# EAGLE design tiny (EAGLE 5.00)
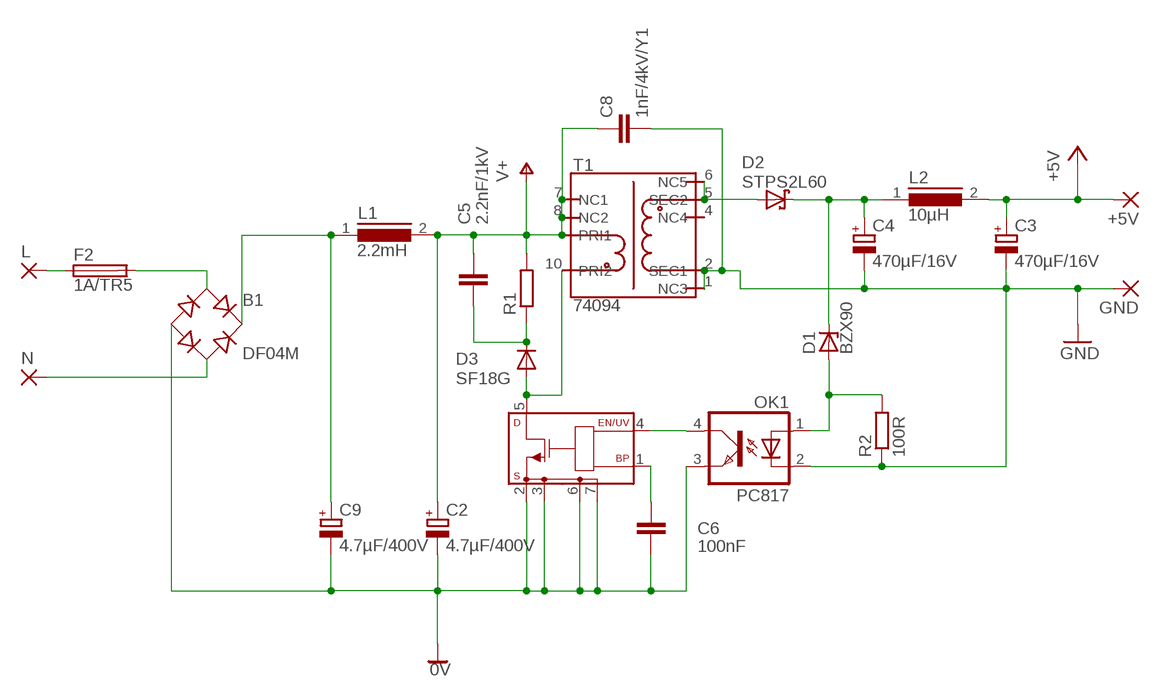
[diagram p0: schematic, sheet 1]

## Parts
+5V  2,54/1,0  [2,54/1,0]
B1  DF04M  B-DIL  [B-DIL]
C2  4.7µF/400V  CPOL-EUE3.5-10  [E3,5-10]
C3  470µF/16V  CPOL-EUE3.5-8  [E3,5-8]
C4  470µF/16V  CPOL-EUE3.5-8  [E3,5-8]
C5  2.2nF/1kV  C-EU075-032X103  [C075-032X103]
C6  100nF  C-EU025-025X050  [C025-025X050]
C8  1nF/4kV/Y1  C-EU102-043X133  [C102-043X133]
C9  4.7µF/400V  CPOL-EUE3.5-10  [E3,5-10]
D1  BZX90  [DO34Z7]
D2  STPS2L60  SCHOTTKY-DIODE  [DO41-7]
D3  SF18G  [DO41-7]
F2  1A/TR5  TR5  [TR5]
GND  2,54/1,0  [2,54/1,0]
IC2  TNY264-268DIP  [DIP-8B]
L  2,54/1,0  [2,54/1,0]
L1  2.2mH  82114R  [82114R]
L2  10µH  82114R  [82114R]
N  2,54/1,0  [2,54/1,0]
OK1  PC817  [DIL04]
R1  R-EU_0207/7  [0207/7]
R2  100R  R-EU_0207/7  [0207/7]
T1  74094  [74094]

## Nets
0V: B1.- C2.- C6.2 C9.- IC2.2(S2) IC2.3(S3) IC2.6(S7) IC2.7(S8) OK1.3(EMIT)
+5V: +5V.1(P) C3.+ L2.2
DRAIN: D3.A IC2.5(D) T1.10(PRI2)
GND: C3.- C4.- C8.2 GND.1(P) OK1.2(C) R2.1 T1.1(NC3) T1.2(SEC1)
N$1: B1.AC1 F2.2
N$2: B1.AC2 N.1(P)
N$3: F2.1 L.1(P)
N$4: B1.+ C9.+ L1.1
N$6: D1.A OK1.1(A) R2.2
N$7: C6.1 IC2.1(BP)
N$8: IC2.4(EN/UV) OK1.4(COL)
N$11: C5.2 D3.C R1.1
N$13: C4.+ D1.C D2.C L2.1
N$15: D2.A T1.5(SEC2) T1.6(NC5)
V+: C2.+ C5.1 C8.1 L1.2 R1.2 T1.7(NC1) T1.8(NC2) T1.9(PRI1)

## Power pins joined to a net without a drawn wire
NC4: T1.4(NC4)

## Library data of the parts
+5V GND L N = wirepad:2,54/1,0: THROUGH-HOLE PAD
B1 = rectifier:B-DIL: RECTIFIER
C2-C4 C9 = rcl:CPOL-EU: POLARIZED CAPACITOR, European symbol
C5 C6 C8 = rcl:C-EU: CAPACITOR, European symbol
D1 = diode:BZX90: Z DIODE
D2 = diode:SCHOTTKY-DIODE: Schottky Diode
D3 = diode:SF18G
F2 = fuse:TR5: FUSE
IC2 = top-switcher:TNY264-268: Enhanced, Energy efficient, Low Power Off-line Switcher ( 0....23W)
L1 L2 = inductors:82114R: INDUCTOR
OK1 = optocoupler:PC817: SHARP OPTO COUPLER
R1 R2 = rcl:R-EU_: RESISTOR, European symbol
T1 = myrra:74094

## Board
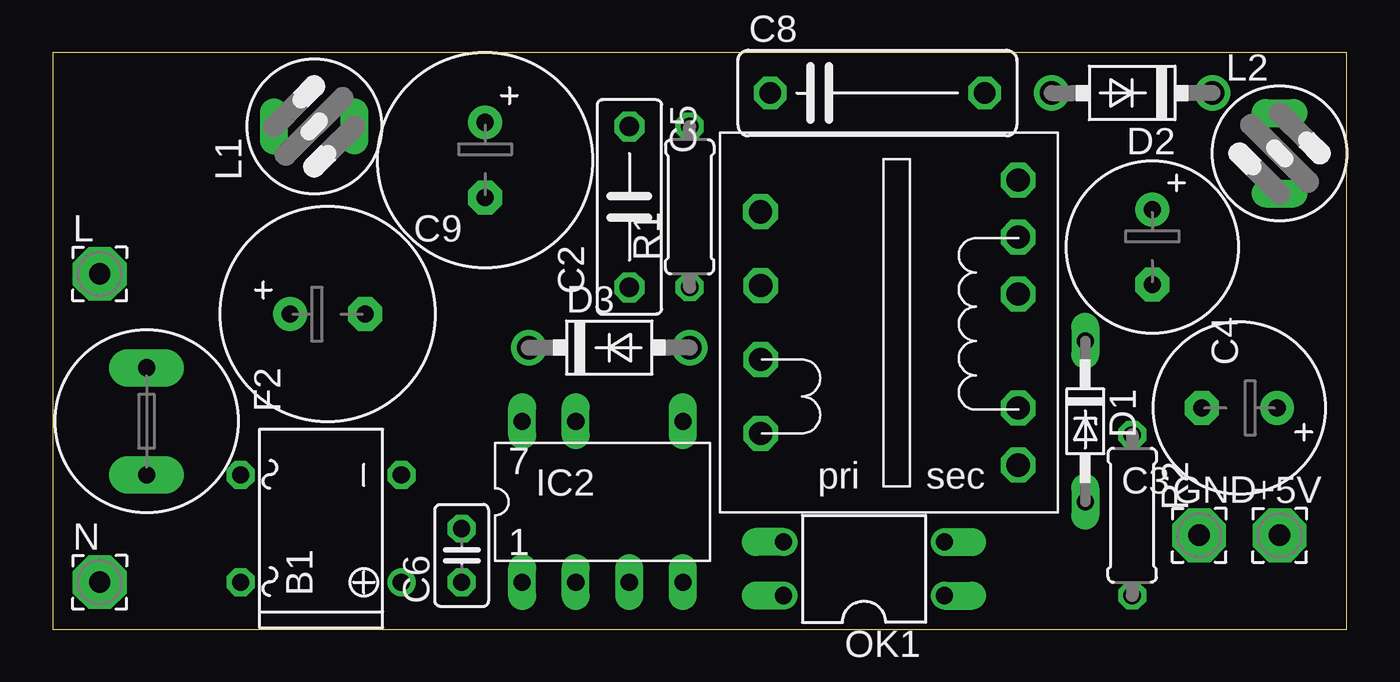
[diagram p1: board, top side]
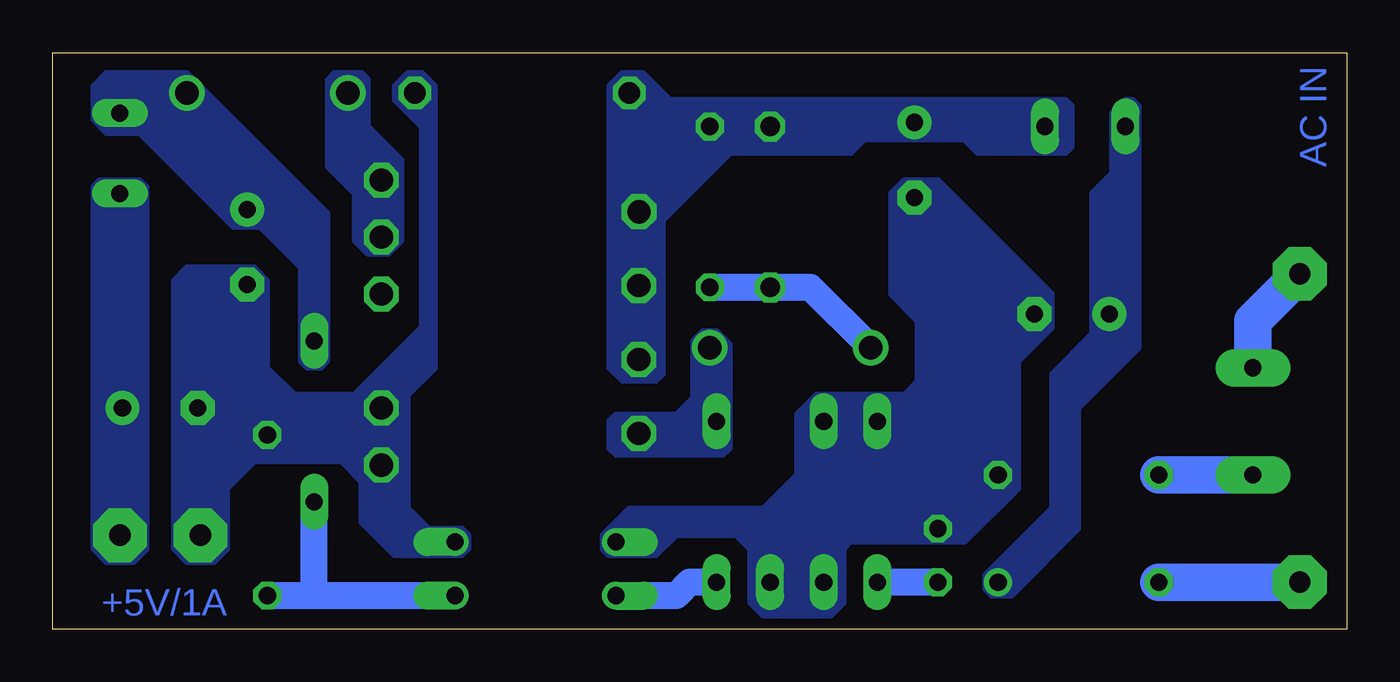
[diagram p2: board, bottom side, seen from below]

Size 61.28 x 27.3 mm. Coordinates in mm from the lower left corner, seen from the top.
Outline: 0,0 61.28,0 61.28,27.3 0,27.3 0,0
Copper layers (1*16): Top 0.035mm / dielectric 1.5mm / Bottom 0.035mm
Design rules "default *": minimum track width 10mil, minimum drill 24mil, track to track 8mil, track to pad 8mil, pad to pad 8mil, via to via 8mil, smd to smd 8mil, copper to edge 20mil, drill to drill 8mil, minimum pad ring 10mil, minimum via ring 8mil, stop-mask expansion 4mil, vias tented up to drill 0mil, thermal gap 10mil

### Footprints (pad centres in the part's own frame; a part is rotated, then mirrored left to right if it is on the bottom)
2,54/1,0 = drill 1.016 pad 2.54 octagon: 1 0,0
B-DIL = drill 0.813 round: + -2.54,-3.81 | drill 0.813 octagon: - 2.54,-3.81; AC1 2.54,3.81; AC2 -2.54,3.81
E3,5-10 = drill 0.813 pad 1.6 round: + -1.778,0 | drill 0.813 pad 1.6 octagon: - 1.778,0
E3,5-8 = drill 0.813 pad 1.6 round: + -1.778,0 | drill 0.813 pad 1.6 octagon: - 1.778,0
C075-032X103 = drill 0.914 octagon: 1 -3.81,0; 2 3.81,0
C025-025X050 = drill 0.813 octagon: 1 -1.27,0; 2 1.27,0
C102-043X133 = drill 1.016 octagon: 1 -5.08,0; 2 5.08,0
DO34Z7 = drill 0.813 long: A 3.81,0; C -3.81,0
DO41-7 = drill 1.118 round: A 3.81,0; C -3.81,0
TR5 = drill 0.813 pad 1.778 long: 1 -2.54,0; 2 2.54,0
DIP-8B = drill 0.813 long: 1 -3.81,-3.81; 2 -1.27,-3.81; 3 1.27,-3.81; 4 3.81,-3.81; 5 3.81,3.81; 6 -1.27,3.81; 7 -3.81,3.81
82114R = drill 0.813 long: 1 0,1.905; 2 0,-1.905
DIL04 = drill 0.813 offset: 1 -1.27,-3.81; 2 1.27,-3.81; 3 1.27,3.81; 4 -1.27,3.81
0207/7 = drill 0.813 octagon: 1 -3.81,0; 2 3.81,0
74094 = drill 1.1 octagon: 1 0,-13.5; 2 0,-10.8; 4 0,-5.4; 5 0,-2.7; 6 0,0; 7 -12.2,-1.5; 8 -12.195,-5; 9 -12.195,-8.5; 10 -12.194,-12

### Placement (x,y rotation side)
+5V  58.1,4.45 0 top
B1  12.7,4.76 90 top
C2  20.48,22.23 270 top
C3  56.2,10.48 180 top
C4  52.07,18.1 270 top
C5  27.3,20 270 top
C6  19.37,3.49 90 top
C8  39.05,25.4 0 top
C9  13.02,14.92 0 top
D1  48.9,9.84 270 top
D2  51.12,25.4 180 top
D3  26.35,13.34 0 top
F2  4.45,9.84 270 top
GND  54.29,4.45 0 top
IC2  26.04,6.03 0 top
L  2.22,16.83 0 top
L1  12.38,23.81 90 top
L2  58.1,22.54 0 top
N  2.22,2.22 0 top
OK1  38.42,2.86 90 top
R1  30.16,20 90 top
R2  51.12,5.4 270 top
T1  45.72,21.27 0 top

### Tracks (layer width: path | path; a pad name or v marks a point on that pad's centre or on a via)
0V
  Bottom 0.406: IC2.7 21.91,9.84
  pour Bottom (no thermals): 34.92,3.49 35.24,3.81 35.24,4.45 33.97,5.71 27.62,5.71 26.04,7.3 26.04,10.16 25.08,11.11 20.95,11.11 20.32,11.75 20.32,14.61 21.59,15.88 21.59,20.64 20.95,21.27 19.37,21.27 13.97,15.88 13.97,14.29 15.56,12.7 15.56,6.67 18.1,4.13 23.5,4.13 23.81,3.81 23.81,1.27 24.45,0.64 27.62,0.64 28.26,1.27 28.26,3.81 28.89,4.45 31.75,4.45 32.7,3.49
+5V
  pour Bottom (no thermals): 59.37,3.81 59.37,20.95 59.05,21.27 57.15,21.27 56.83,20.95 56.83,3.81 57.47,3.17 58.74,3.17
DRAIN
  pour Bottom (no thermals): 29.53,8.26 34.61,8.26 34.92,8.57 34.92,9.84 34.61,10.16 31.75,10.16 30.96,10.95 30.96,13.65 30.48,14.13 29.84,14.13 29.21,13.49 29.21,8.57
GND
  pour Bottom (no thermals): 54.93,17.14 51.75,17.14 51.12,16.51 51.12,12.38 49.85,11.11 46.99,11.11 43.81,14.29 43.81,23.81 45.09,25.08 45.09,25.72 44.45,26.35 43.81,26.35 43.18,25.72 43.18,12.38 44.45,11.11 44.45,5.71 43.5,4.76 41.91,4.76 41.59,4.45 41.59,3.81 41.91,3.49 45.09,3.49 46.67,5.08 46.67,6.99 47.62,7.94 51.75,7.94 53.02,6.67 53.02,3.81 53.66,3.17 54.93,3.17 55.56,3.81 55.56,16.51
N$1
  Bottom 1.778: F2.2 B1.AC1
N$2
  Bottom 1.778: N.1 B1.AC2
N$3
  Bottom 1.778: L.1 4.45,14.61 F2.1
N$4
  pour Bottom (no thermals): 12.7,4.76 12.7,10.48 9.84,13.34 9.84,24.77 10.16,25.08 10.48,25.08 11.11,24.45 11.11,21.59 12.06,20.64 12.06,13.97 13.97,12.06 13.97,5.71 17.14,2.54 17.14,1.91 16.83,1.59 15.88,1.59
N$6
  Bottom 0.61: R2.2 48.9,1.91
  Bottom 1.27: 48.9,1.91 D1.A | OK1.1 R2.2
N$7
  Bottom 1.27: C6.1 IC2.1
N$8
  Bottom 1.27: OK1.4 31.75,1.59 31.11,2.22 IC2.4
N$11
  Bottom 1.27: D3.C 25.4,16.19 C5.2 R1.1
N$13
  pour Bottom (no thermals): 48.26,19.68 54.93,26.35 58.74,26.35 59.37,25.72 59.37,24.13 58.74,23.5 57.15,23.5 52.7,19.05 51.44,19.05 49.53,17.14 49.53,12.7 49.21,12.38 48.58,12.38 48.26,12.7
N$15
  pour Bottom (no thermals): 45.4,17.78 44.77,18.41 44.77,22.23 46.35,23.81 46.35,26.04 46.67,26.35 47.94,26.35 48.26,26.04 48.26,21.91 46.99,20.64 46.99,18.41 46.35,17.78
V+
  pour Bottom (no thermals): 13.34,22.54 13.02,22.86 13.02,24.77 13.34,25.08 32.07,25.08 33.34,26.35 34.29,26.35 34.92,25.72 34.92,12.38 34.29,11.75 32.7,11.75 32.38,12.06 32.38,19.37 29.21,22.54 23.5,22.54 22.86,23.18 18.1,23.18 17.46,22.54

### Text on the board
Bottom: AC IN | +5V/1A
